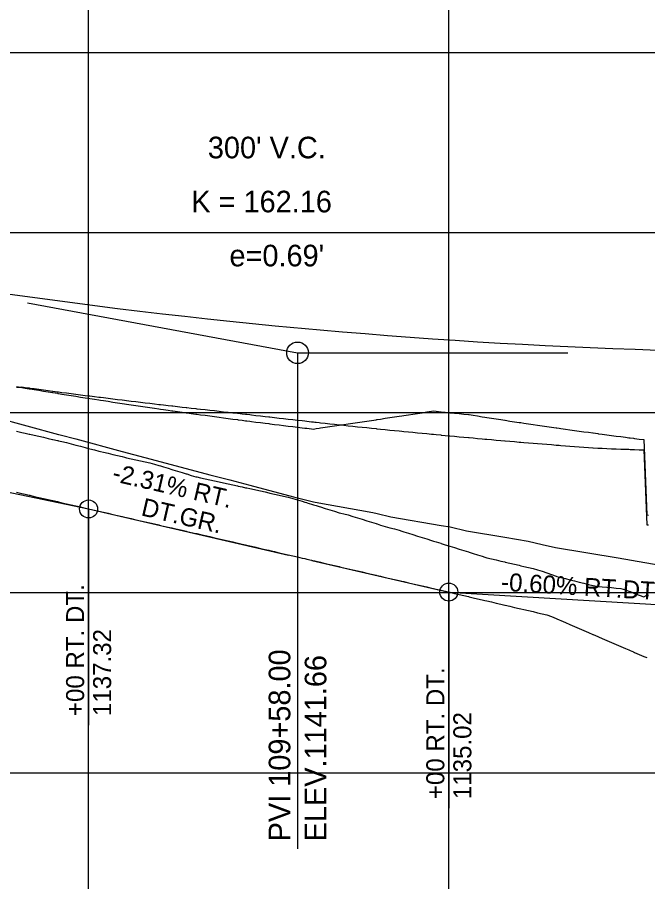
# Model space of a CAD drawing. Extents: x 688474 to 694748, y 765018 to 767373.
# Drawn here: x 691833.8 to 692008.8, y 765929.6 to 766169.7 of the extents above; entities that cross this region are included whole.
import ezdxf

# ---------------------------------------------------------------- set-up
doc = ezdxf.new("R2010")
doc.units = 0
for name, color, linetype in [('37', 7, 'Continuous'), ('R_Exist Surface', 7, 'Continuous'), ('R_Profile Work Left', 7, 'Continuous'), ('R_Profile Work Right', 7, 'Continuous'), ('R_Vert Alg', 7, 'Continuous'), ('R_Vert Alg Annot', 7, 'Continuous')]:
    doc.layers.add(name, color=color, linetype=linetype)

msp = doc.modelspace()

# ---------------------------------------------------------------- linework, layer by layer
at = {"layer": '37'}
for p, q in [((691853.59, 765809.92), (691853.59, 766359.92)), ((691953.59, 765809.92), (691953.59, 766359.92)), ((690853.59, 766159.92), (693453.59, 766159.92)), ((690853.59, 766109.92), (693453.59, 766109.92)), ((690853.59, 766059.92), (693453.59, 766059.92)), ((690853.59, 766009.92), (693453.59, 766009.92)), ((690853.59, 765959.92), (693453.59, 765959.92))]:
    msp.add_line(p, q, dxfattribs=at)
at = {"layer": 'R_Exist Surface'}
msp.add_lwpolyline([(691827.54, 766058.65), (691845.24, 766053.87), (691845.65, 766053.76), (691850.02, 766052.61), (691862.94, 766049.15), (691869.21, 766047.47), (691880.64, 766044.42), (691887.23, 766042.67), (691892.83, 766041.22), (691898.34, 766039.75), (691910.44, 766036.56), (691916.04, 766035.11), (691916.46, 766035), (691932.5, 766032.18), (691933.73, 766031.88), (691937.46, 766031.01), (691951.43, 766028.58), (691953.94, 766028.15), (691958.47, 766027.1), (691969.13, 766025.29), (691975.62, 766024.19), (691979.52, 766023.3), (691983.24, 766022.44), (692000.61, 766019.59), (692013.83, 766017.31)], dxfattribs=at)
at = {"layer": 'R_Profile Work Left'}
for points in [[(691833.59, 766067.15), (691834.67, 766066.97), (691835.09, 766066.9), (691835.95, 766066.75), (691837.13, 766066.56), (691837.23, 766066.54), (691838.51, 766066.33), (691839.79, 766066.11), (691841.08, 766065.9), (691842.36, 766065.69), (691843.59, 766065.49), (691843.64, 766065.49), (691844.92, 766065.28), (691845.09, 766065.25), (691845.24, 766065.23), (691846.2, 766065.07), (691847.49, 766064.86), (691848.77, 766064.66), (691850.05, 766064.46), (691851.33, 766064.25), (691852.61, 766064.05), (691853.59, 766063.9), (691853.9, 766063.85), (691855.18, 766063.65), (691856.46, 766063.45), (691856.93, 766063.38), (691857.74, 766063.25), (691859.02, 766063.06), (691860.31, 766062.86), (691861.59, 766062.67), (691862.87, 766062.47), (691862.94, 766062.46), (691863.59, 766062.37), (691864.15, 766062.28), (691865.43, 766062.09), (691866.72, 766061.9), (691868, 766061.71), (691869.28, 766061.52), (691870.56, 766061.33), (691871.84, 766061.15), (691873.13, 766060.96), (691873.59, 766060.89), (691874.41, 766060.78), (691875.69, 766060.59), (691876.73, 766060.45), (691876.97, 766060.41), (691878.25, 766060.23), (691879.54, 766060.05), (691880.64, 766059.89), (691880.82, 766059.87), (691882.1, 766059.69), (691883.38, 766059.51), (691883.59, 766059.49), (691884.67, 766059.34), (691885.95, 766059.16), (691887.23, 766058.99), (691888.51, 766058.81), (691889.79, 766058.64), (691891.08, 766058.47), (691892.36, 766058.3), (691893.59, 766058.14), (691893.64, 766058.13), (691894.92, 766057.96), (691895.13, 766057.94), (691896.2, 766057.8), (691897.15, 766057.67), (691897.49, 766057.63), (691898.34, 766057.52), (691898.77, 766057.46), (691900.05, 766057.3), (691901.33, 766057.14), (691902.61, 766056.97), (691903.59, 766056.85), (691903.9, 766056.81), (691905.18, 766056.65), (691906.46, 766056.49), (691907.74, 766056.34), (691909.02, 766056.18), (691910.31, 766056.02), (691911.59, 766055.87), (691912.87, 766055.71), (691913.59, 766055.63), (691914.15, 766055.56), (691914.18, 766055.56), (691915.43, 766055.41), (691916.04, 766055.34), (691916.38, 766055.45), (691916.72, 766055.5), (691917.57, 766055.62), (691918, 766055.68), (691919.28, 766055.87), (691920.56, 766056.05), (691921.84, 766056.24), (691923.13, 766056.43), (691923.59, 766056.49), (691924.41, 766056.61), (691925.69, 766056.8), (691926.97, 766056.99), (691928.25, 766057.18), (691929.54, 766057.37), (691930.82, 766057.56), (691932.1, 766057.75), (691933.38, 766057.94), (691933.59, 766057.98), (691933.73, 766058), (691934.67, 766058.14), (691935.95, 766058.33), (691937.23, 766058.52), (691938.51, 766058.72), (691939.79, 766058.91), (691940.59, 766059.03), (691941.08, 766059.11), (691942.36, 766059.3), (691943.59, 766059.49), (691943.64, 766059.5), (691944.92, 766059.7), (691946.2, 766059.9), (691947.49, 766060.1), (691948.77, 766060.29), (691949.3, 766060.38), (691950.05, 766060.3), (691951.33, 766060.16), (691951.43, 766060.15), (691952.61, 766060.03), (691953.59, 766059.93), (691953.9, 766059.9), (691955.18, 766059.77), (691956.46, 766059.64), (691957.74, 766059.51), (691959.02, 766059.39), (691959.27, 766059.36), (691960.31, 766059.19), (691961.59, 766058.99), (691962.87, 766058.78), (691963.59, 766058.67), (691963.61, 766058.67), (691964.15, 766058.58), (691965.43, 766058.38), (691966.72, 766058.18), (691968, 766057.98), (691969.13, 766057.8), (691969.28, 766057.78), (691970.56, 766057.58), (691971.84, 766057.39), (691973.13, 766057.2), (691973.59, 766057.13), (691974.41, 766057), (691975.69, 766056.81), (691976.97, 766056.62), (691978.25, 766056.43), (691979.54, 766056.25), (691980.82, 766056.06), (691982.1, 766055.87), (691983.38, 766055.69), (691983.59, 766055.66), (691984.23, 766055.57), (691984.67, 766055.51), (691985.95, 766055.33), (691987.23, 766055.15), (691988.51, 766054.97), (691989.79, 766054.79), (691991.08, 766054.61), (691992.36, 766054.44), (691993.59, 766054.27), (691993.64, 766054.26), (691994.92, 766054.09), (691995.12, 766054.06), (691996.2, 766053.92), (691997.49, 766053.75), (691998.77, 766053.58), (692000.05, 766053.41), (692001.33, 766053.24), (692002.61, 766053.07), (692003.59, 766052.95), (692003.9, 766052.91), (692004.83, 766052.79), (692005.18, 766052.75), (692006.46, 766052.58), (692007.74, 766052.42), (692008.59, 766031.54), (692009.02, 766031.46)], [(691833.59, 766054.77), (691834.67, 766054.52), (691835.09, 766054.43), (691835.95, 766054.23), (691837.13, 766053.96), (691837.23, 766053.94), (691838.51, 766053.64), (691839.79, 766053.35), (691841.08, 766053.06), (691842.36, 766052.76), (691843.59, 766052.48), (691843.64, 766052.47), (691844.92, 766052.18), (691845.09, 766052.14), (691845.24, 766052.1), (691846.2, 766051.88), (691847.49, 766051.58), (691848.77, 766051.25), (691850.05, 766050.91), (691851.33, 766050.57), (691852.61, 766050.24), (691853.59, 766049.98), (691853.9, 766049.9), (691855.18, 766049.56), (691856.46, 766049.23), (691856.93, 766049.1), (691857.74, 766048.91), (691859.02, 766048.61), (691860.31, 766048.31), (691861.59, 766048), (691862.87, 766047.7), (691862.94, 766047.69), (691863.59, 766047.53), (691864.15, 766047.4), (691865.43, 766047.11), (691866.72, 766046.82), (691868, 766046.53), (691869.28, 766046.24), (691870.56, 766045.95), (691871.84, 766045.64), (691873.13, 766045.24), (691873.59, 766045.1), (691874.41, 766044.85), (691875.69, 766044.46), (691876.73, 766044.14), (691876.97, 766044.06), (691878.25, 766043.67), (691879.54, 766043.27), (691880.64, 766042.93), (691880.82, 766042.88), (691882.1, 766042.48), (691883.38, 766042.09), (691883.59, 766042.05), (691884.67, 766041.81), (691885.95, 766041.53), (691887.23, 766041.25), (691888.51, 766040.97), (691889.79, 766040.68), (691891.08, 766040.4), (691892.36, 766040.12), (691893.59, 766039.85), (691893.64, 766039.84), (691894.92, 766039.56), (691895.13, 766039.51), (691896.2, 766039.28), (691897.15, 766039.07), (691897.49, 766039), (691898.34, 766038.81), (691898.77, 766038.71), (691900.05, 766038.43), (691901.33, 766038.15), (691902.61, 766037.87), (691903.59, 766037.65), (691903.9, 766037.59), (691905.18, 766037.31), (691906.46, 766037.02), (691907.74, 766036.74), (691909.02, 766036.46), (691910.31, 766036.11), (691911.59, 766035.72), (691912.87, 766035.32), (691913.59, 766035.09), (691914.15, 766034.91), (691914.18, 766034.9), (691915.43, 766034.51), (691916.04, 766034.31), (691916.38, 766034.21), (691916.72, 766034.11), (691917.57, 766033.84), (691918, 766033.71), (691919.28, 766033.31), (691920.56, 766032.92), (691921.84, 766032.52), (691923.13, 766032.12), (691923.59, 766031.99), (691924.41, 766031.8), (691925.69, 766031.5), (691926.97, 766031.1), (691928.25, 766030.7), (691929.54, 766030.3), (691930.82, 766029.9), (691932.1, 766029.5), (691933.38, 766029.1), (691933.59, 766029.03), (691933.73, 766028.99), (691934.67, 766028.7), (691935.95, 766028.3), (691937.23, 766027.9), (691938.51, 766027.61), (691939.79, 766027.24), (691940.59, 766026.99), (691941.08, 766026.84), (691942.36, 766026.44), (691943.59, 766026.05), (691943.64, 766026.03), (691944.92, 766025.63), (691946.2, 766025.22), (691947.49, 766024.82), (691948.77, 766024.41), (691949.3, 766024.25), (691950.05, 766024.01), (691951.33, 766023.62), (691951.43, 766023.58), (691952.61, 766023.22), (691953.59, 766022.92), (691953.9, 766022.82), (691955.18, 766022.42), (691956.46, 766022.03), (691957.74, 766021.63), (691959.02, 766021.23), (691959.27, 766021.16), (691960.31, 766020.83), (691961.59, 766020.44), (691962.87, 766020.03), (691963.59, 766019.78), (691963.61, 766019.78), (691964.15, 766019.59), (691965.43, 766019.29), (691966.72, 766018.99), (691968, 766018.7), (691969.13, 766018.43), (691969.28, 766018.4), (691970.56, 766018.1), (691971.84, 766017.81), (691973.13, 766017.51), (691973.59, 766017.41), (691974.41, 766017.22), (691975.69, 766016.92), (691976.97, 766016.63), (691978.25, 766016.3), (691979.54, 766015.84), (691980.82, 766015.39), (691982.1, 766014.94), (691983.38, 766014.48), (691983.59, 766014.41), (691984.23, 766014.25), (691984.67, 766014.14), (691985.95, 766013.81), (691987.23, 766013.49), (691988.51, 766013.16), (691989.79, 766012.84), (691991.08, 766012.51), (691992.36, 766012.19), (691993.59, 766011.88), (691993.64, 766011.86), (691994.92, 766011.64), (691995.12, 766011.63), (691996.2, 766011.53), (691997.49, 766011.42), (691998.77, 766011.31), (692000.05, 766011.2), (692001.33, 766011.09), (692002.61, 766010.68), (692003.59, 766010.32), (692003.9, 766010.2), (692004.83, 766009.85), (692005.18, 766009.72), (692006.46, 766009.24), (692007.74, 766008.76), (692008.59, 766009.22), (692009.02, 766009.19)]]:
    msp.add_lwpolyline(points, dxfattribs=at)
at = {"layer": 'R_Profile Work Right'}
for points in [[(691833.59, 766066.95), (691834.67, 766067.02), (691835.09, 766067.05), (691835.95, 766066.93), (691837.13, 766066.76), (691837.23, 766066.75), (691838.51, 766066.58), (691839.79, 766066.4), (691841.08, 766066.22), (691842.36, 766066.05), (691843.59, 766065.88), (691843.64, 766065.88), (691844.92, 766065.7), (691845.09, 766065.68), (691845.24, 766065.66), (691846.2, 766065.54), (691847.49, 766065.37), (691848.77, 766065.21), (691850.05, 766065.04), (691851.33, 766064.88), (691852.61, 766064.71), (691853.59, 766064.59), (691853.9, 766064.55), (691855.18, 766064.39), (691856.46, 766064.23), (691856.93, 766064.17), (691857.74, 766064.07), (691859.02, 766063.91), (691860.31, 766063.75), (691861.59, 766063.6), (691862.87, 766063.44), (691862.94, 766063.43), (691863.59, 766063.35), (691864.15, 766063.28), (691865.43, 766063.13), (691866.72, 766062.97), (691868, 766062.82), (691869.28, 766062.67), (691870.56, 766062.51), (691871.84, 766062.36), (691873.13, 766062.21), (691873.59, 766062.16), (691874.41, 766062.06), (691875.69, 766061.91), (691876.73, 766061.79), (691876.97, 766061.76), (691878.25, 766061.61), (691879.54, 766061.47), (691880.64, 766061.34), (691880.82, 766061.32), (691882.1, 766061.17), (691883.38, 766061.03), (691883.59, 766061.01), (691884.67, 766060.88), (691885.95, 766060.74), (691887.23, 766060.6), (691888.51, 766060.46), (691889.79, 766060.31), (691891.08, 766060.17), (691892.36, 766060.03), (691893.59, 766059.9), (691893.64, 766059.9), (691894.92, 766059.76), (691895.13, 766059.73), (691896.2, 766059.61), (691897.15, 766059.49), (691897.49, 766059.45), (691898.34, 766059.35), (691898.77, 766059.3), (691900.05, 766059.15), (691901.33, 766059), (691902.61, 766058.85), (691903.59, 766058.74), (691903.9, 766058.7), (691905.18, 766058.55), (691906.46, 766058.4), (691907.74, 766058.26), (691909.02, 766058.11), (691910.31, 766057.97), (691911.59, 766057.82), (691912.87, 766057.68), (691913.59, 766057.6), (691914.15, 766057.53), (691914.18, 766057.53), (691915.43, 766057.39), (691916.04, 766057.32), (691916.38, 766057.29), (691916.72, 766057.25), (691917.57, 766057.16), (691918, 766057.11), (691919.28, 766056.97), (691920.56, 766056.83), (691921.84, 766056.69), (691923.13, 766056.55), (691923.59, 766056.5), (691924.41, 766056.41), (691925.69, 766056.28), (691926.97, 766056.14), (691928.25, 766056.01), (691929.54, 766055.87), (691930.82, 766055.74), (691932.1, 766055.61), (691933.38, 766055.47), (691933.59, 766055.45), (691933.73, 766055.44), (691934.67, 766055.34), (691935.95, 766055.21), (691937.23, 766055.08), (691938.51, 766054.95), (691939.79, 766054.82), (691940.59, 766054.75), (691941.08, 766054.7), (691942.36, 766054.57), (691943.59, 766054.45), (691943.64, 766054.44), (691944.92, 766054.32), (691946.2, 766054.19), (691947.49, 766054.07), (691948.77, 766053.95), (691949.3, 766053.9), (691950.05, 766053.82), (691951.33, 766053.7), (691951.43, 766053.69), (691952.61, 766053.58), (691953.59, 766053.49), (691953.9, 766053.46), (691955.18, 766053.34), (691956.46, 766053.22), (691957.74, 766053.11), (691959.02, 766052.99), (691959.27, 766052.97), (691960.31, 766052.87), (691961.59, 766052.76), (691962.87, 766052.64), (691963.59, 766052.58), (691963.61, 766052.58), (691964.15, 766052.53), (691965.43, 766052.41), (691966.72, 766052.3), (691968, 766052.19), (691969.13, 766052.09), (691969.28, 766052.08), (691970.56, 766051.97), (691971.84, 766051.86), (691973.13, 766051.75), (691973.59, 766051.71), (691974.41, 766051.64), (691975.69, 766051.54), (691976.97, 766051.43), (691978.25, 766051.33), (691979.54, 766051.22), (691980.82, 766051.12), (691982.1, 766051.02), (691983.38, 766050.92), (691983.59, 766050.9), (691984.23, 766050.85), (691984.67, 766050.82), (691985.95, 766050.72), (691987.23, 766050.62), (691988.51, 766050.53), (691989.79, 766050.43), (691991.08, 766050.34), (691992.36, 766050.24), (691993.59, 766050.16), (691993.64, 766050.15), (691994.92, 766050.06), (691995.12, 766050.05), (691996.2, 766050), (691997.49, 766049.95), (691998.77, 766049.9), (692000.05, 766049.85), (692001.33, 766049.8), (692002.61, 766049.76), (692003.59, 766049.72), (692003.9, 766049.71), (692004.83, 766049.68), (692005.18, 766049.66), (692006.46, 766049.62), (692007.74, 766049.58), (692008.59, 766028.72), (692009.02, 766028.71)], [(691833.59, 766037.79), (691834.67, 766037.55), (691835.09, 766037.45), (691835.95, 766037.25), (691837.13, 766036.98), (691837.23, 766036.96), (691838.51, 766036.66), (691839.79, 766036.37), (691841.08, 766036.07), (691842.36, 766035.78), (691843.59, 766035.5), (691843.64, 766035.48), (691844.92, 766035.19), (691845.09, 766035.15), (691845.24, 766035.12), (691846.2, 766034.89), (691847.49, 766034.6), (691848.77, 766034.31), (691850.05, 766034.01), (691851.33, 766033.72), (691852.61, 766033.42), (691853.59, 766033.2), (691853.9, 766033.13), (691855.18, 766032.83), (691856.46, 766032.54), (691856.93, 766032.43), (691857.74, 766032.24), (691859.02, 766031.95), (691860.31, 766031.65), (691861.59, 766031.36), (691862.87, 766031.06), (691862.94, 766031.05), (691863.59, 766030.9), (691864.15, 766030.77), (691865.43, 766030.47), (691866.72, 766030.18), (691868, 766029.89), (691869.28, 766029.59), (691870.56, 766029.3), (691871.84, 766029), (691873.13, 766028.71), (691873.59, 766028.6), (691874.41, 766028.41), (691875.69, 766028.12), (691876.73, 766027.88), (691876.97, 766027.82), (691878.25, 766027.53), (691879.54, 766027.23), (691880.64, 766026.98), (691880.82, 766026.94), (691882.1, 766026.64), (691883.38, 766026.35), (691883.59, 766026.3), (691884.67, 766026.05), (691885.95, 766025.76), (691887.23, 766025.47), (691888.51, 766025.17), (691889.79, 766024.88), (691891.08, 766024.58), (691892.36, 766024.29), (691893.59, 766024), (691893.64, 766023.99), (691894.92, 766023.7), (691895.13, 766023.65), (691896.2, 766023.4), (691897.15, 766023.18), (691897.49, 766023.1), (691898.34, 766022.9), (691898.77, 766022.8), (691900.05, 766022.51), (691901.33, 766022.21), (691902.61, 766021.91), (691903.59, 766021.69), (691903.9, 766021.61), (691905.18, 766021.32), (691906.46, 766021.02), (691907.74, 766020.72), (691909.02, 766020.42), (691910.31, 766020.13), (691911.59, 766019.83), (691912.87, 766019.53), (691913.59, 766019.36), (691914.15, 766019.23), (691914.18, 766019.23), (691915.43, 766018.93), (691916.04, 766018.8), (691916.38, 766018.71), (691916.72, 766018.64), (691917.57, 766018.44), (691918, 766018.34), (691919.28, 766018.04), (691920.56, 766017.74), (691921.84, 766017.45), (691923.13, 766017.15), (691923.59, 766017.04), (691924.41, 766016.85), (691925.69, 766016.55), (691926.97, 766016.26), (691928.25, 766015.96), (691929.54, 766015.66), (691930.82, 766015.36), (691932.1, 766015.07), (691933.38, 766014.77), (691933.59, 766014.72), (691933.73, 766014.69), (691934.67, 766014.47), (691935.95, 766014.17), (691937.23, 766013.88), (691938.51, 766013.58), (691939.79, 766013.28), (691940.59, 766013.1), (691941.08, 766012.98), (691942.36, 766012.69), (691943.59, 766012.4), (691943.64, 766012.39), (691944.92, 766012.09), (691946.2, 766011.79), (691947.49, 766011.5), (691948.77, 766011.2), (691949.3, 766011.07), (691950.05, 766010.9), (691951.33, 766010.6), (691951.43, 766010.58), (691952.61, 766010.31), (691953.59, 766010.08), (691953.9, 766010.01), (691955.18, 766009.71), (691956.46, 766009.41), (691957.74, 766009.12), (691959.02, 766008.82), (691959.27, 766008.76), (691960.31, 766008.52), (691961.59, 766008.22), (691962.87, 766007.93), (691963.59, 766007.76), (691963.61, 766007.76), (691964.15, 766007.63), (691965.43, 766007.33), (691966.72, 766007.03), (691968, 766006.74), (691969.13, 766006.47), (691969.28, 766006.44), (691970.56, 766006.14), (691971.84, 766005.84), (691973.13, 766005.54), (691973.59, 766005.43), (691974.41, 766005.24), (691975.69, 766004.94), (691976.97, 766004.64), (691978.25, 766004.34), (691979.54, 766004.04), (691980.82, 766003.74), (691982.1, 766003.27), (691983.38, 766002.71), (691983.59, 766002.63), (691984.23, 766002.35), (691984.67, 766002.16), (691985.95, 766001.61), (691987.23, 766001.06), (691988.51, 766000.51), (691989.79, 765999.95), (691991.08, 765999.4), (691992.36, 765998.85), (691993.59, 765998.32), (691993.64, 765998.3), (691994.92, 765997.75), (691995.12, 765997.66), (691996.2, 765997.2), (691997.49, 765996.64), (691998.77, 765996.09), (692000.05, 765995.54), (692001.33, 765994.99), (692002.61, 765994.44), (692003.59, 765994.02), (692003.9, 765993.88), (692004.83, 765993.48), (692005.18, 765993.33), (692006.46, 765992.78), (692007.74, 765992.23), (692008.59, 765991.87)]]:
    msp.add_lwpolyline(points, dxfattribs=at)
at = {"layer": 'R_Vert Alg'}
for p, q in [((691836.59, 766090.41), (691911.59, 766076.52)), ((691911.59, 766076.52), (691986.59, 766076.52)), ((691753.59, 766053.97), (691853.59, 766033.15)), ((691853.59, 766033.15), (691909.06, 766020.36)), ((691915.54, 766018.86), (691953.59, 766010.08)), ((691953.59, 766010.08), (692058.59, 766003.78))]:
    msp.add_line(p, q, dxfattribs=at)
msp.add_lwpolyline([(691830.34, 766093.02), (691836.59, 766092.14), (691842.84, 766091.29), (691849.09, 766090.46), (691855.34, 766089.65), (691861.59, 766088.86), (691867.84, 766088.1), (691874.09, 766087.37), (691880.34, 766086.66), (691886.59, 766085.97), (691892.84, 766085.31), (691899.09, 766084.67), (691905.34, 766084.05), (691917.84, 766082.9), (691924.09, 766082.35), (691930.34, 766081.84), (691936.59, 766081.34), (691942.84, 766080.87), (691949.09, 766080.43), (691955.34, 766080), (691961.59, 766079.61), (691967.84, 766079.23), (691974.09, 766078.88), (691980.34, 766078.56), (691986.59, 766078.26), (691992.84, 766077.98), (691999.09, 766077.73), (692005.34, 766077.5), (692011.59, 766077.29)], dxfattribs=at)
for centre, radius in [((691911.59, 766076.52), 3), ((691853.59, 766033.15), 2.5), ((691953.59, 766010.08), 2.5)]:
    msp.add_circle(centre, radius, dxfattribs=at)
at = {"layer": 'R_Vert Alg Annot'}
for p, q in [((691911.59, 766076.52), (691911.59, 765938.81)), ((691853.59, 766033.15), (691853.59, 765973.15)), ((691953.59, 766010.08), (691953.59, 765950.08))]:
    msp.add_line(p, q, dxfattribs=at)

# ---------------------------------------------------------------- texts
for s, p in [("300' V.C.", (691886.69, 766130.53)), ('K = 162.16', (691882.1, 766115.53)), ("e=0.69'", (691892.69, 766100.53))]:
    msp.add_text(s, height=6, dxfattribs=at).set_placement(p)
for s, height, rotation, p in [('-2.31% RT.', 5, 347.0069, (691859.88, 766040.97)), ('DT.GR.', 5, 347.0069, (691867.93, 766031.41)), ('-0.60% RT.DT.GR.', 5, 356.5641, (691967.98, 766010.47)), ('+00 RT. DT.', 5, 90, (691852.34, 765975.65)), ('1137.32', 5, 90, (691859.84, 765975.65)), ('PVI 109+58.00', 6, 90, (691909.59, 765940.85)), ('ELEV.1141.66', 6, 90, (691919.59, 765940.85)), ('+00 RT. DT.', 5, 90, (691952.34, 765952.58)), ('1135.02', 5, 90, (691959.84, 765952.58))]:
    msp.add_text(s, height=height, rotation=rotation, dxfattribs=at).set_placement(p)

doc.saveas('drawing.dxf')
